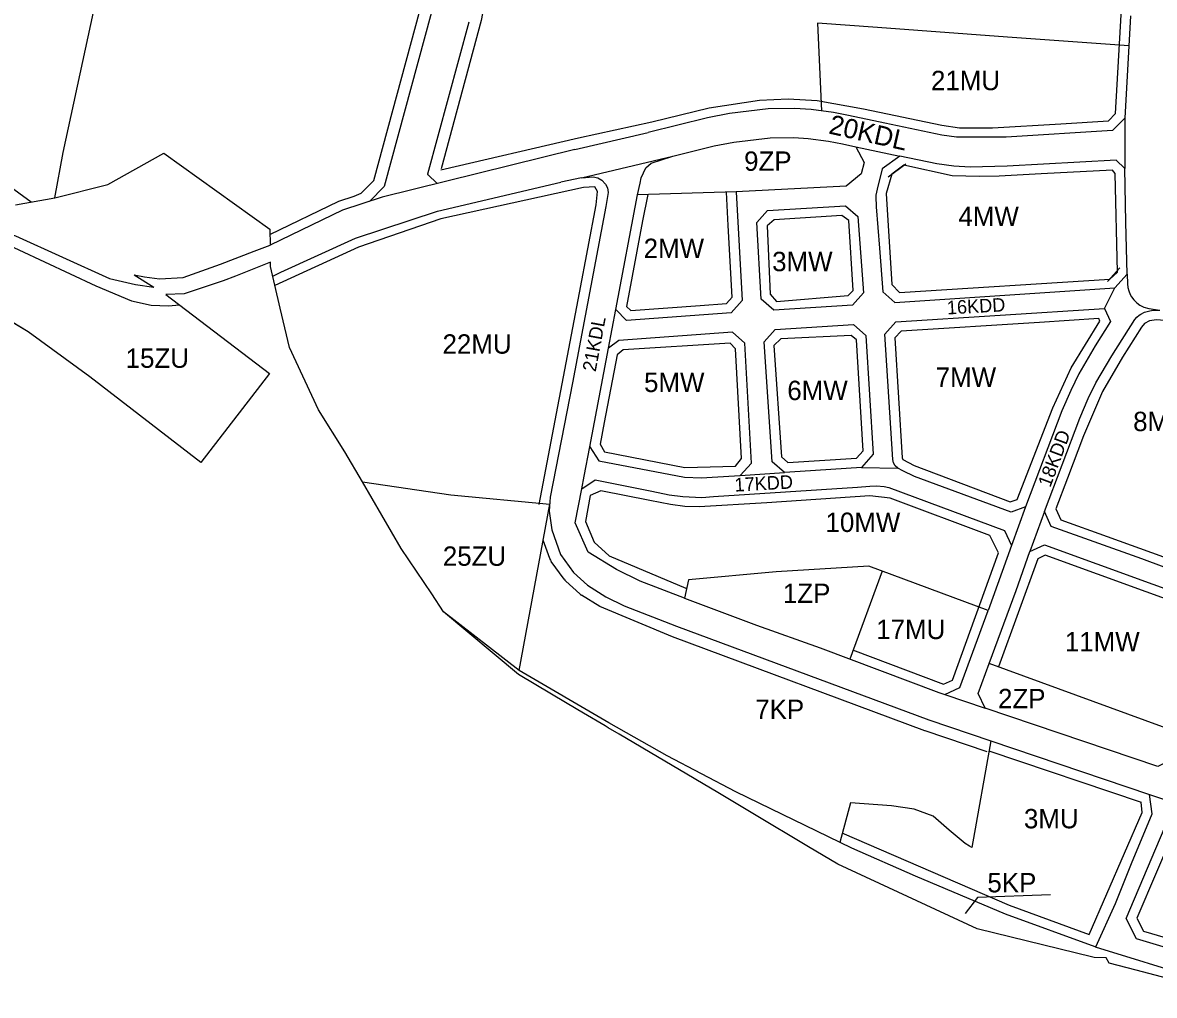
# Model space of a CAD drawing. Extents: x 7428203 to 7432868, y 5542672 to 5545406.
# Drawn here: x 7431420 to 7432004, y 5542894 to 5543396 of the extents above; entities that cross this region are included whole.
import ezdxf

# ---------------------------------------------------------------- set-up
doc = ezdxf.new("R2010")
doc.units = 0
for name, color, linetype in [('granica_planu', 7, 'Continuous'), ('linie_rozgraniczajace', 7, 'Continuous'), ('linie_zabudowy_nieprzekraczalne', 7, 'Continuous'), ('oznaczenia_przeznaczen', 7, 'Continuous')]:
    doc.layers.add(name, color=color, linetype=linetype)

msp = doc.modelspace()

# ---------------------------------------------------------------- linework, layer by layer
at = {"layer": 'granica_planu'}
msp.add_lwpolyline([(7432011.22, 5542902.36), (7431994.8, 5542906.65), (7431980.87, 5542910.28), (7431979.3, 5542912.96), (7431973.07, 5542913.08), (7431972.47, 5542913.23), (7431912.76, 5542927.96), (7431840.69, 5542961.29), (7431825.57, 5542970.33), (7431796.77, 5542987.57), (7431778.7, 5542998.39), (7431727.75, 5543028.47), (7431722.11, 5543031.79), (7431720.58, 5543032.7), (7431709.41, 5543039.33), (7431700.89, 5543044.38), (7431675.9, 5543059.21), (7431637.05, 5543091.63), (7431630.97, 5543100.97), (7431615.19, 5543124.31), (7431595.28, 5543158.86), (7431586.13, 5543174.25), (7431572.47, 5543195.93), (7431557.55, 5543228.24), (7431552.77, 5543248.55), (7431547.75, 5543269.92), (7431547.72, 5543271.35), (7431547.71, 5543271.92), (7431547.71, 5543272.32), (7431529.68, 5543265.09), (7431523.35, 5543262.55), (7431503.11, 5543255.89), (7431493.62, 5543255.54), (7431547.16, 5543214.78), (7431511.7, 5543168.81), (7431454.36, 5543213.02), (7431422.59, 5543236.25), (7431389.74, 5543255.95)], dxfattribs=at)
at = {"layer": 'linie_rozgraniczajace'}
for p, q in [((7431650.15, 5543396.15), (7431628.87, 5543317.63)), ((7431991.84, 5543399.38), (7431988.98, 5543346.68)), ((7431784.79, 5543349.01), (7431773.48, 5543346.73)), ((7431804.81, 5543351.43), (7431784.79, 5543349.01)), ((7431818.35, 5543351.62), (7431804.81, 5543351.43)), ((7431826.9, 5543351.11), (7431818.35, 5543351.62)), ((7431838.44, 5543349.6), (7431826.9, 5543351.11)), ((7431846.26, 5543347.95), (7431838.44, 5543349.6)), ((7431865.06, 5543343.99), (7431846.26, 5543347.95)), ((7431773.48, 5543346.73), (7431742.73, 5543339.14)), ((7431894.42, 5543337.81), (7431865.06, 5543343.99)), ((7431988.98, 5543346.68), (7431982.63, 5543340.29)), ((7431704.98, 5543330.36), (7431742.73, 5543339.14)), ((7431787.04, 5543334.17), (7431805.82, 5543336.44)), ((7431805.82, 5543336.44), (7431818.01, 5543336.62)), ((7431818.01, 5543336.62), (7431825.48, 5543336.17)), ((7431825.48, 5543336.17), (7431835.92, 5543334.8)), ((7431902.1, 5543336.77), (7431894.42, 5543337.81)), ((7431927.62, 5543336.75), (7431902.1, 5543336.77)), ((7431982.63, 5543340.29), (7431927.62, 5543336.75)), ((7431704.98, 5543330.36), (7431605.47, 5543305.81)), ((7431755.54, 5543326.92), (7431776.87, 5543332.31)), ((7431776.87, 5543332.31), (7431787.04, 5543334.17)), ((7431835.92, 5543334.8), (7431843.17, 5543333.27)), ((7431843.17, 5543333.27), (7431850.09, 5543331.81)), ((7431850.09, 5543331.81), (7431872.83, 5543327.03)), ((7431850.09, 5543331.81), (7431854.37, 5543323.64)), ((7431708.38, 5543315.74), (7431755.54, 5543326.92)), ((7431744.38, 5543323.34), (7431755.54, 5543326.92)), ((7431739.11, 5543315.76), (7431741.63, 5543320.87)), ((7431741.63, 5543320.87), (7431744.38, 5543323.34)), ((7431854.37, 5543323.64), (7431852.77, 5543317.91)), ((7431628.96, 5543317.55), (7431633.8, 5543312.8)), ((7431708.38, 5543315.74), (7431697.64, 5543313.47)), ((7431708.38, 5543315.74), (7431714.42, 5543316.36)), ((7431714.42, 5543316.36), (7431716.87, 5543315.78)), ((7431716.87, 5543315.78), (7431718.9, 5543314.51)), ((7431718.9, 5543314.51), (7431720.73, 5543312.55)), ((7431720.73, 5543312.55), (7431721.82, 5543310.61)), ((7431737.2, 5543307.03), (7431738.59, 5543313.05)), ((7431738.59, 5543313.05), (7431739.11, 5543315.76)), ((7431852.77, 5543317.91), (7431845.04, 5543311.44)), ((7431722.15, 5543308.2), (7431720.88, 5543301)), ((7431721.82, 5543310.61), (7431722.15, 5543308.2)), ((7431726.17, 5543247.73), (7431737.2, 5543307.03)), ((7431788.19, 5543308.51), (7431737.2, 5543307.03)), ((7431845.04, 5543311.44), (7431788.19, 5543308.51)), ((7431788.19, 5543308.51), (7431791.27, 5543252.4)), ((7431605.47, 5543305.81), (7431584.92, 5543299.03)), ((7431720.88, 5543301), (7431703.66, 5543209.89)), ((7431584.92, 5543299.03), (7431547.5, 5543281)), ((7431547.71, 5543272.32), (7431529.68, 5543265.09)), ((7431547.71, 5543271.92), (7431547.71, 5543272.32)), ((7431547.72, 5543271.35), (7431547.71, 5543271.92)), ((7431547.75, 5543269.92), (7431547.72, 5543271.35)), ((7431477.33, 5543265.7), (7431487.44, 5543259.4)), ((7431552.77, 5543248.55), (7431547.75, 5543269.92)), ((7431523.35, 5543262.55), (7431503.11, 5543255.89)), ((7431529.68, 5543265.09), (7431523.35, 5543262.55)), ((7431422.59, 5543236.25), (7431389.74, 5543255.95)), ((7431503.11, 5543255.89), (7431493.62, 5543255.54)), ((7431493.62, 5543255.54), (7431547.16, 5543214.78)), ((7431978.52, 5543248.35), (7431983.83, 5543258.99)), ((7431557.55, 5543228.24), (7431552.77, 5543248.55)), ((7431791.27, 5543252.4), (7431785.69, 5543245.99)), ((7431722.36, 5543227.81), (7431726.17, 5543247.73)), ((7431731.52, 5543242.13), (7431726.17, 5543247.73)), ((7431785.69, 5543245.99), (7431731.52, 5543242.13)), ((7431454.36, 5543213.02), (7431422.59, 5543236.25)), ((7431572.47, 5543195.93), (7431557.55, 5543228.24)), ((7431712.61, 5543176.78), (7431722.36, 5543227.81)), ((7431511.7, 5543168.81), (7431454.36, 5543213.02)), ((7431547.16, 5543214.78), (7431511.7, 5543168.81)), ((7431703.66, 5543209.89), (7431692.26, 5543150.94)), ((7431586.13, 5543174.25), (7431572.47, 5543195.93)), ((7431595.28, 5543158.86), (7431586.13, 5543174.25)), ((7431709.72, 5543161.69), (7431712.61, 5543176.78)), ((7431708.45, 5543155.18), (7431709.72, 5543161.69)), ((7431615.19, 5543124.31), (7431595.28, 5543158.86)), ((7431705.12, 5543137.59), (7431708.45, 5543155.18)), ((7431676.21, 5543061.35), (7431691.99, 5543147.31)), ((7431937.69, 5543145.87), (7431930.46, 5543125.87)), ((7431711.76, 5543122.53), (7431705.12, 5543137.59)), ((7431630.97, 5543100.97), (7431615.19, 5543124.31)), ((7431863.58, 5543112.73), (7431846.95, 5543067.25)), ((7431637.05, 5543091.63), (7431630.97, 5543100.97)), ((7431721, 5543099.47), (7431730.42, 5543094.82)), ((7431675.9, 5543059.21), (7431637.05, 5543091.63)), ((7431730.42, 5543094.82), (7431757.44, 5543084.31)), ((7431757.44, 5543084.31), (7431887.8, 5543035.86)), ((7432017.85, 5543028.79), (7431919, 5543064.95)), ((7431700.89, 5543044.38), (7431675.9, 5543059.21)), ((7431709.41, 5543039.33), (7431700.89, 5543044.38)), ((7431896.06, 5543048.9), (7431916.9, 5543041.85)), ((7431720.58, 5543032.7), (7431709.41, 5543039.33)), ((7431722.11, 5543031.79), (7431720.58, 5543032.7)), ((7431727.75, 5543028.47), (7431722.11, 5543031.79)), ((7431887.8, 5543035.86), (7431919.79, 5543025.03)), ((7431778.7, 5542998.39), (7431727.75, 5543028.47)), ((7431919.79, 5543025.03), (7431909.97, 5542969.91)), ((7431796.77, 5542987.57), (7431778.7, 5542998.39)), ((7432001.68, 5542997.32), (7432063.09, 5542976.74)), ((7431825.57, 5542970.33), (7431796.77, 5542987.57)), ((7431989.67, 5542933.23), (7432011.78, 5542985.25)), ((7431840.69, 5542961.29), (7431825.57, 5542970.33)), ((7431912.76, 5542927.96), (7431840.69, 5542961.29)), ((7431995.04, 5542922.73), (7431989.67, 5542933.23)), ((7431972.47, 5542913.23), (7431912.76, 5542927.96)), ((7432019.53, 5542915.43), (7431995.04, 5542922.73)), ((7431973.07, 5542913.08), (7431972.47, 5542913.23)), ((7431979.3, 5542912.96), (7431973.07, 5542913.08)), ((7431980.87, 5542910.28), (7431979.3, 5542912.96)), ((7431994.8, 5542906.65), (7431980.87, 5542910.28)), ((7432011.22, 5542902.36), (7431994.8, 5542906.65))]:
    msp.add_line(p, q, dxfattribs=at)
for points in [[(7431436.3, 5543305.53), (7431440.68, 5543328.86), (7431476.66, 5543495.49), (7431506.81, 5543625.52)], [(7431667.23, 5543590.08), (7431645.7, 5543477.8), (7431630.84, 5543401.36), (7431606.51, 5543311.31), (7431598.84, 5543303.62)], [(7431991, 5543383.88), (7431928.42, 5543388.5), (7431861.27, 5543393.45), (7431830.25, 5543395.73), (7431832.25, 5543350.41)], [(7431988.98, 5543346.68), (7431989.03, 5543320.57), (7431984.56, 5543324.99), (7431928.27, 5543321.77), (7431909.17, 5543321.34), (7431900.66, 5543321.83), (7431891.87, 5543323.02), (7431872.83, 5543327.03), (7431863.73, 5543320.36), (7431861.05, 5543309.9), (7431860.44, 5543306.88), (7431860.38, 5543306.1), (7431860.47, 5543300.79), (7431862.3, 5543279.55), (7431863.93, 5543256.98), (7431870.26, 5543251.36), (7431983.83, 5543258.99), (7431990.16, 5543266.02), (7431989.49, 5543292.86), (7431989.03, 5543320.57)], [(7431415.94, 5543301.93), (7431436.35, 5543305.54), (7431463.65, 5543312.41), (7431492.57, 5543328.57), (7431547.32, 5543289.35), (7431547.5, 5543281)], [(7431591.58, 5543284.69), (7431634.06, 5543298.65), (7431697.64, 5543313.47)], [(7431383.66, 5543294.77), (7431401.55, 5543290.86), (7431416.06, 5543285.83), (7431464.51, 5543263.85), (7431478.05, 5543260.69), (7431487.44, 5543259.4)], [(7431384.15, 5543294.67), (7431390.98, 5543291.05), (7431457.43, 5543259.96)], [(7431548.9, 5543265.04), (7431553.05, 5543267.04), (7431591.58, 5543284.69)], [(7431477.33, 5543265.7), (7431482.72, 5543264.73), (7431490.43, 5543263.67), (7431502.66, 5543264.27), (7431521.83, 5543271.16), (7431539.28, 5543278), (7431547.5, 5543281)], [(7431990.16, 5543266.02), (7431990.37, 5543261.06), (7431990.58, 5543259.1), (7431990.97, 5543257.51), (7431991.75, 5543255.57), (7431992.43, 5543254.34), (7431993.59, 5543252.77), (7431995.11, 5543251.25), (7431996.69, 5543250.09), (7431998.75, 5543249.03), (7432001.46, 5543248.23), (7432006.98, 5543247.37)], [(7431457.43, 5543259.96), (7431475.95, 5543252.27), (7431486.04, 5543250.05), (7431495.11, 5543249.75), (7431500.69, 5543250.16)], [(7431852.94, 5543166.25), (7431871.67, 5543165.86), (7431870.35, 5543167.08), (7431869.56, 5543168.57), (7431869.08, 5543170.32), (7431865.01, 5543235), (7431870.79, 5543241.37), (7431978.52, 5543248.35), (7431981.64, 5543241.54), (7431973.75, 5543229.07), (7431965.27, 5543214.61), (7431961.01, 5543205.95), (7431956.42, 5543195.38), (7431937.69, 5543145.87), (7431930.2, 5543143.04), (7431880.3, 5543161.59), (7431874.35, 5543164.47), (7431871.67, 5543165.86)], [(7432032.45, 5543106.16), (7431997.81, 5543118.94), (7431950.96, 5543135.72), (7431947.45, 5543143.42), (7431965.69, 5543191.62), (7431970.09, 5543201.75), (7431974.08, 5543209.86), (7431982.29, 5543223.86), (7431994.13, 5543242.58), (7431995.19, 5543243.87), (7431996.41, 5543244.83), (7431997.28, 5543245.45), (7431999.07, 5543246.35), (7432001.23, 5543246.99), (7432003.48, 5543247.42), (7432006.98, 5543247.37)], [(7431790.38, 5543162.09), (7431813.29, 5543163.58), (7431806.9, 5543169.18), (7431802.72, 5543231.14), (7431808.31, 5543237.5), (7431848.84, 5543240.01), (7431855.15, 5543234.39), (7431858.96, 5543173.07), (7431852.94, 5543166.25), (7431821.28, 5543164.1), (7431813.29, 5543163.58)], [(7431712.61, 5543176.78), (7431717.36, 5543169.7), (7431761.61, 5543161.14), (7431770.39, 5543160.8), (7431775.88, 5543161.15), (7431790.38, 5543162.09), (7431796.13, 5543168.48), (7431792.75, 5543230.45), (7431786.36, 5543236.01), (7431727.71, 5543231.83), (7431722.36, 5543227.81)], [(7431595.28, 5543158.86), (7431640.84, 5543152.09), (7431691.99, 5543147.31)], [(7431708.45, 5543155.18), (7431715.48, 5543159.88), (7431744.71, 5543153.96), (7431753.69, 5543152.14), (7431760.73, 5543151.17), (7431770.52, 5543150.78), (7431776.53, 5543151.17), (7431850.99, 5543156.01), (7431857.35, 5543156.63), (7431860.71, 5543156.74), (7431864.67, 5543156.37), (7431867.13, 5543155.82), (7431926.83, 5543133.62), (7431930.46, 5543125.87), (7431918.41, 5543092.32), (7431856.75, 5543115.27), (7431808.89, 5543112.26), (7431763.62, 5543108.23), (7431761.6, 5543098.78), (7431738.65, 5543107.49), (7431726.48, 5543113.5), (7431711.76, 5543122.53)], [(7431692.26, 5543150.94), (7431691.71, 5543143.67), (7431693.03, 5543134.07), (7431697.59, 5543121.2), (7431704.23, 5543111.96), (7431711.5, 5543105.36), (7431721, 5543099.47)], [(7431947.45, 5543143.42), (7431939.96, 5543122.74), (7431947.58, 5543126.31), (7432030.55, 5543096.2), (7432035.1, 5543088.13), (7432028.11, 5543060.23), (7432017.85, 5543028.79), (7432013.51, 5543015.49), (7432005.96, 5543011.7), (7431916.9, 5543041.85), (7431913.29, 5543049.4), (7431919, 5543064.95), (7431932.86, 5543102.67), (7431939.96, 5543122.74)], [(7431761.6, 5543098.78), (7431798.71, 5543084.7), (7431831.66, 5543073), (7431892.84, 5543049.99), (7431896.06, 5543048.9), (7431903.81, 5543052.61), (7431918.41, 5543092.32)], [(7431973.61, 5542918.72), (7431927.43, 5542935.57), (7431880.83, 5542955.06), (7431848.05, 5542969.53), (7431788, 5542998.67), (7431752.6, 5543017.22), (7431722.5, 5543034.34), (7431676.21, 5543061.35), (7431637.05, 5543091.63)], [(7431919.79, 5543025.03), (7432001.68, 5542997.32)], [(7431973.93, 5542918.62), (7431984.23, 5542941.05), (7431992.43, 5542961.69), (7432003.03, 5542987.3), (7432001.68, 5542997.32)], [(7431909.97, 5542969.91), (7431908.8, 5542970.62), (7431906.46, 5542972.01), (7431898.21, 5542978.82), (7431889.92, 5542986.2), (7431880.26, 5542989.77), (7431868.45, 5542991.54), (7431847.25, 5542993.09), (7431841.76, 5542972.58)], [(7431973.61, 5542918.72), (7432026.26, 5542902.45), (7432052.98, 5542896.69)]]:
    msp.add_lwpolyline(points, dxfattribs=at)
msp.add_lwpolyline([(7431804.45, 5543298.95), (7431844.68, 5543301.4), (7431851.1, 5543295.77), (7431853.95, 5543256.36), (7431848.3, 5543250), (7431807.64, 5543247.47), (7431801.24, 5543253.09), (7431798.95, 5543292.68)], close=True, dxfattribs=at)
msp.add_ellipse((7431629.16, 5543317.7), major_axis=(0.3137, 0.0125), ratio=0.64301469, start_param=3.44605043, end_param=3.9667194, dxfattribs=at)
at = {"layer": 'linie_zabudowy_nieprzekraczalne'}
for p, q in [((7431984.1, 5543349.02), (7431988.54, 5543424.24)), ((7431774.35, 5543352), (7431800.26, 5543355.92)), ((7431800.26, 5543355.92), (7431815.15, 5543356.58)), ((7431815.15, 5543356.58), (7431830.13, 5543355.73)), ((7431830.13, 5543355.73), (7431853.94, 5543351.44)), ((7431744.68, 5543344.77), (7431774.35, 5543352)), ((7431853.94, 5543351.44), (7431894.43, 5543342.91)), ((7431980.59, 5543345.18), (7431984.1, 5543349.02)), ((7431365.58, 5543344.99), (7431424.16, 5543303.46)), ((7431706.78, 5543336.52), (7431744.68, 5543344.77)), ((7431894.43, 5543342.91), (7431903.59, 5543341.69)), ((7431903.59, 5543341.69), (7431920.61, 5543341.6)), ((7431920.61, 5543341.6), (7431955.99, 5543343.62)), ((7431955.99, 5543343.62), (7431980.59, 5543345.18)), ((7431635.66, 5543319.86), (7431706.78, 5543336.52)), ((7431866.68, 5543316.33), (7431875.79, 5543322.99)), ((7431980.12, 5543262.33), (7431986.44, 5543269.36)), ((7431691.93, 5543119.2), (7431688.57, 5543128.69)), ((7431699.35, 5543108.46), (7431692.72, 5543117.7)), ((7431707.46, 5543100.92), (7431700.19, 5543107.52)), ((7431717.84, 5543094.37), (7431708.34, 5543100.26)), ((7431755.35, 5543078.69), (7431717.84, 5543094.37)), ((7431885.71, 5543030.24), (7431755.35, 5543078.69)), ((7431917.87, 5543019.35), (7431885.88, 5543030.18))]:
    msp.add_line(p, q, dxfattribs=at)
for points in [[(7431594.59, 5543307.86), (7431601.14, 5543314.41), (7431625, 5543402.72), (7431639.8, 5543478.94), (7431661.34, 5543591.21)], [(7431694.1, 5543592.69), (7431674.64, 5543491.6), (7431660.37, 5543416.96), (7431656.51, 5543397.07), (7431635.8, 5543320.41)], [(7431547.39, 5543286.47), (7431583.04, 5543303.68), (7431590.91, 5543306.31), (7431594.59, 5543307.86)], [(7431686.51, 5543147.12), (7431707.36, 5543256.37), (7431715.97, 5543301.93), (7431716.56, 5543308.66), (7431715.25, 5543311.09), (7431709.41, 5543310.85), (7431635.75, 5543294.63), (7431593.15, 5543279.94), (7431549.9, 5543260.1)], [(7431742.58, 5543307.19), (7431739.87, 5543293.62), (7431731.52, 5543249.36), (7431733.81, 5543247.3), (7431769.63, 5543249.85), (7431783.27, 5543250.83), (7431786.15, 5543254.13), (7431784.03, 5543291.23), (7431783.19, 5543308.37)], [(7432034.39, 5543113.14), (7432043.73, 5543188.67), (7432048.44, 5543232.45), (7432044.91, 5543236.73), (7432009.4, 5543242.19), (7432005.32, 5543242.44), (7432001.75, 5543241.93), (7431999.15, 5543240.63), (7431997.6, 5543238.7), (7431987.79, 5543223.21), (7431977.48, 5543205.45), (7431967.63, 5543182.62), (7431959.31, 5543160.62), (7431953.35, 5543144.87), (7431955.89, 5543139.22), (7431979.8, 5543130.62), (7432031.84, 5543111.71), (7432034.42, 5543113.41)], [(7431899.93, 5543056.33), (7431923.81, 5543122.08), (7431919.28, 5543131.09), (7431867.71, 5543150.27), (7431857.2, 5543151.59), (7431804, 5543147.95), (7431769.07, 5543145.84), (7431761.65, 5543146.13), (7431754.37, 5543147), (7431743.62, 5543149.08), (7431718.39, 5543154.19), (7431712.87, 5543151.67), (7431710.34, 5543138.31), (7431714.98, 5543127.62), (7431722.6, 5543120.5), (7431762.28, 5543103.87)], [(7432013.15, 5543030.51), (7432029.77, 5543087.41), (7432027.1, 5543092.15), (7431947.8, 5543120.89), (7431943.97, 5543119.1), (7431923.69, 5543063.23)], [(7431848.27, 5543071.99), (7431895.3, 5543054.31), (7431899.93, 5543056.33)], [(7431997.52, 5542993.23), (7431918.84, 5543019.67)], [(7431842.83, 5542977.53), (7431929.29, 5542940.21), (7431970.57, 5542924.97), (7431997.9, 5542987.96), (7431997.34, 5542993.4)], [(7432023.88, 5542984.66), (7432015.52, 5542980.91), (7431995.17, 5542933.46), (7431998.58, 5542926.78), (7432020.96, 5542920.22), (7432052.26, 5542917.94), (7432057.44, 5542919.56), (7432066.42, 5542919.52), (7432164.7, 5542893.58)]]:
    msp.add_lwpolyline(points, dxfattribs=at)
for points in [[(7431913.93, 5543316.44), (7431899.83, 5543316.89), (7431874.9, 5543322.34), (7431868.64, 5543317.76), (7431865.7, 5543307.67), (7431868.67, 5543260.75), (7431872.52, 5543256.51), (7431981.16, 5543263.49), (7431985.13, 5543266.99), (7431984.07, 5543318.06), (7431982.7, 5543319.79), (7431945.82, 5543317.9), (7431924.13, 5543316.67)], [(7431846.48, 5543293.73), (7431842.86, 5543296.28), (7431807.79, 5543294.16), (7431804.18, 5543291.06), (7431805.75, 5543255.79), (7431809.01, 5543251.9), (7431846.1, 5543255.05), (7431848.75, 5543257.6)], [(7431976.06, 5543241.72), (7431975.54, 5543243.14), (7431944.93, 5543241.11), (7431873.44, 5543236.53), (7431870.14, 5543233.22), (7431874.05, 5543171.21), (7431874.3, 5543170.3), (7431880.24, 5543167.18), (7431929.79, 5543148.52), (7431933.41, 5543149.6), (7431951.72, 5543197.09), (7431961.25, 5543217.63)], [(7431729.84, 5543226.97), (7431726.79, 5543224.36), (7431720.12, 5543189.49), (7431717.97, 5543178.19), (7431720.29, 5543174.3), (7431761.75, 5543166.17), (7431787.94, 5543166.85), (7431791.03, 5543170.81), (7431787.94, 5543227.46), (7431785.1, 5543230.47)], [(7431811.27, 5543232.67), (7431807.67, 5543229.19), (7431811.74, 5543171.72), (7431815, 5543168.73), (7431850.47, 5543171), (7431853.89, 5543174.73), (7431850.37, 5543232.12), (7431847.57, 5543234.44)]]:
    msp.add_lwpolyline(points, close=True, dxfattribs=at)
for centre, radius, start, end in [((7431697.3716, 5543121.1079), 5.7664, 199.3211617, 216.2274007), ((7431705.0047, 5543112.6678), 7.0485, 216.6539358, 226.9150962), ((7431712.0182, 5543106.0809), 6.8856, 228.5486406, 237.7115641)]:
    msp.add_arc(centre, radius, start, end, dxfattribs=at)
at = {"layer": 'oznaczenia_przeznaczen'}
msp.add_lwpolyline([(7431950.59, 5542945.57), (7431912.96, 5542944.04), (7431906.44, 5542935.84)], dxfattribs=at)

# ---------------------------------------------------------------- texts
for s, p in [('21MU', (7431888.8632, 5543361.06)), ('9ZP', (7431792.349, 5543319.41)), ('4MW', (7431903.0469, 5543290.93)), ('2MW', (7431740.4669, 5543274.38)), ('3MW', (7431806.8269, 5543267.58)), ('22MU', (7431636.5732, 5543224.98)), ('15ZU', (7431472.9128, 5543217.66)), ('5MW', (7431740.6669, 5543205.16)), ('7MW', (7431891.3069, 5543207.84)), ('6MW', (7431814.6569, 5543201.01)), ('8MW', (7431993.2869, 5543184.98)), ('10MW', (7431834.3937, 5543132.89)), ('25ZU', (7431636.7428, 5543115.43)), ('1ZP', (7431812.389, 5543096.23)), ('17MU', (7431860.5732, 5543077.59)), ('11MW', (7431958.0137, 5543071.24)), ('2ZP', (7431923.499, 5543041.86)), ('7KP', (7431798.0942, 5543036.3)), ('3MU', (7431936.8664, 5542979.85)), ('5KP', (7431918.0042, 5542946.77))]:
    msp.add_text(s, height=10, dxfattribs=at).set_placement(p)
for s, height, rotation, p in [('20KDL', 10, 347.321977, (7431835.5705, 5543338.7603)), ('16KDD', 7, 3.1598867, (7431897.285, 5543245.2128)), ('21KDL', 7, 79.464189, (7431715.6843, 5543215.3386)), ('18KDD', 7, 69.4247416, (7431950.469, 5543155.5732)), ('17KDD', 7, 3.1598867, (7431787.585, 5543153.7128))]:
    msp.add_text(s, height=height, rotation=rotation, dxfattribs=at).set_placement(p)

doc.saveas('drawing.dxf')
